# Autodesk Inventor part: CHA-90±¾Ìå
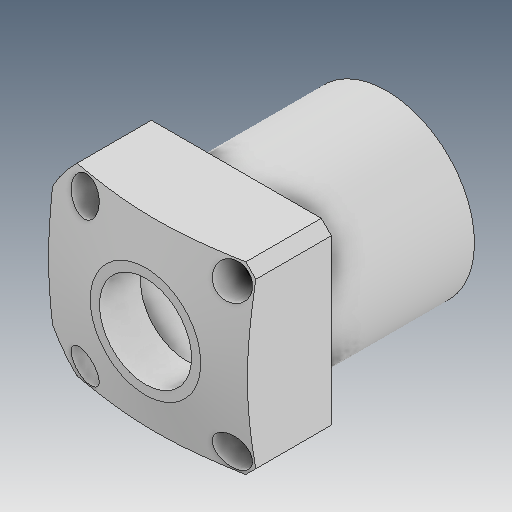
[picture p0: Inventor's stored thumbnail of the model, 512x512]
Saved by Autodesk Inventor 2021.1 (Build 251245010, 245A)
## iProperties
Created: 2019-12
Part Number: CHA-90±¾Ìå
Material: Ogólny
Document SubType Name: Modeling
Designer: user
Density: 1 g/cm^3
Appearance: Domyślna
Author: user
Revision Number: ÈÎºÎ
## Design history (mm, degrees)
feature "ÇÐ³ý-À­Éì7"
node "Bryła1"
